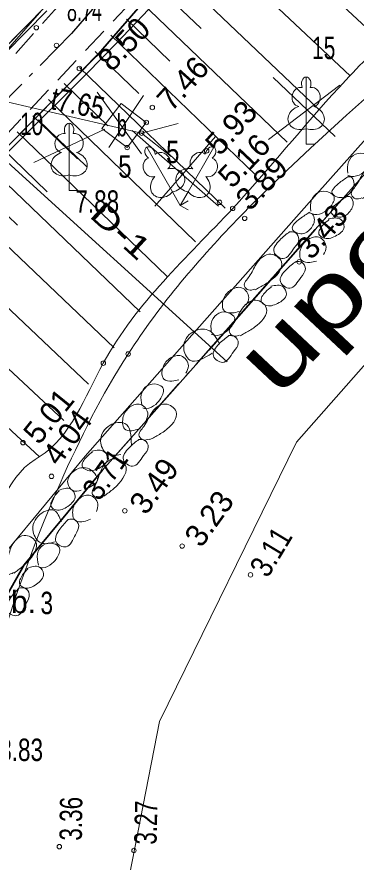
# Model space of a CAD drawing. Extents: x 514052 to 514314, y 297701 to 297876.
# Drawn here: x 514244.06 to 514251.62, y 297772.58 to 297791.45 of the extents above; entities that cross this region are included whole.
import ezdxf
from ezdxf.enums import TextEntityAlignment as Align

# ---------------------------------------------------------------- set-up
doc = ezdxf.new("R2010")
doc.units = 0
doc.header["$LTSCALE"] = 0.2
doc.linetypes.add('DOT_DASHED', pattern=[7.7, 5, -1.2, 0.3, -1.2])
doc.linetypes.add('MEDIUM_DASHED', pattern=[4.5, 3, -1.5])
for name, color, linetype, lineweight in [('1', 7, 'Continuous', 13), ('11', 7, 'Continuous', 35), ('19', 7, 'Continuous', 25), ('28', 7, 'Continuous', 13), ('3', 7, 'Continuous', 13), ('35', 7, 'Continuous', 25), ('5', 7, 'Continuous', 13), ('55', 7, 'Continuous', 13), ('56', 7, 'Continuous', 13), ('6', 7, 'Continuous', 13), ('61', 7, 'Continuous', 13), ('62', 7, 'Continuous', 13), ('63', 7, 'Continuous', 13)]:
    doc.layers.add(name, color=color, linetype=linetype, lineweight=lineweight)
for name, color, linetype in [('12', 7, 'Continuous'), ('15', 7, 'Continuous'), ('27', 7, 'Continuous'), ('8', 7, 'Continuous')]:
    doc.layers.add(name, color=color, linetype=linetype)

msp = doc.modelspace()

# ---------------------------------------------------------------- linework, layer by layer
at = {"layer": '1'}
for p, q in [((514248.911, 297793.941), (514252.207, 297790.881)), ((514248.228, 297793.211), (514251.49, 297790.135)), ((514247.54, 297792.484), (514250.781, 297789.394)), ((514247.195, 297792.123), (514248.166, 297791.194)), ((514246.849, 297791.762), (514250.084, 297788.657)), ((514246.502, 297791.401), (514247.472, 297790.467)), ((514246.155, 297791.041), (514249.39, 297787.917)), ((514245.808, 297790.682), (514246.779, 297789.741)), ((514245.46, 297790.323), (514248.705, 297787.181)), ((514245.112, 297789.963), (514246.09, 297789.017)), ((514244.765, 297789.604), (514248.043, 297786.429)), ((514244.417, 297789.245), (514245.409, 297788.285)), ((514244.069, 297788.886), (514247.41, 297785.654)), ((514243.722, 297788.526), (514244.737, 297787.546)), ((514243.375, 297788.166), (514246.81, 297784.865)), ((514243.028, 297787.805), (514244.075, 297786.803)), ((514242.683, 297787.444), (514246.229, 297784.064)), ((514241.994, 297786.719), (514245.66, 297783.255)), ((514241.309, 297785.99), (514245.105, 297782.443)), ((514240.629, 297785.257), (514244.562, 297781.634))]:
    msp.add_line(p, q, dxfattribs=at)
at = {"layer": '1', "lineweight": 35}
msp.add_line((514241.977, 297789.912), (514248.75, 297783.755), dxfattribs=at)
at = {"layer": '1'}
msp.add_spline([(514260.862, 297805.466), (514258.749, 297804.839), (514257.459, 297803.011), (514254.953, 297800.933), (514250.105, 297795.245), (514240.136, 297784.718), (514236.07, 297778.812), (514235.246, 297774.955), (514233.92, 297771.109), (514234.456, 297764.804)], degree=3, dxfattribs=at)
at = {"layer": '19', "lineweight": 13}
msp.add_spline([(514243.205, 297765.058), (514242.936, 297773.769), (514245.025, 297781.038), (514246.54, 297783.925), (514249.054, 297787.013), (514257.225, 297795.21), (514260.154, 297798.886), (514267.863, 297801.516), (514273.305, 297805.826), (514276.583, 297807.615)], degree=3, dxfattribs=at)
at = {"layer": '28'}
msp.add_lwpolyline([(514247.653, 297789.07), (514246.842, 297788.857), (514247.499, 297788.336)], dxfattribs=at)
at = {"layer": '3'}
msp.add_line((514226.333, 297793.626), (514246.842, 297788.857), dxfattribs=at)
at = {"layer": '35'}
msp.add_lwpolyline([(514231.97, 297771.331), (514233.541, 297774.128), (514233.667, 297780.485), (514240.255, 297787.177), (514246.843, 297793.868), (514250.774, 297798.68), (514254.387, 297803.352), (514256.058, 297805.511), (514258.694, 297808.915), (514260.151, 297809.248), (514268.632, 297811.186)], dxfattribs=at)
at = {"layer": '35', "lineweight": 35}
msp.add_lwpolyline([(514271.3, 297810.152), (514259.606, 297807.499), (514252.681, 297798.474), (514245.829, 297790.57), (514238.515, 297783.139), (514236.323, 297779.764), (514235.19, 297775.821), (514235.133, 297773.758), (514233.372, 297770.559)], dxfattribs=at)
at = {"layer": '5'}
for p, q in [((514250.51, 297790.109), (514250.51, 297788.956)), ((514250.6, 297789.877), (514250.599, 297789.878)), ((514245.225, 297789.079), (514245.225, 297787.926)), ((514250.51, 297788.956), (514250.51, 297788.609)), ((514245.315, 297788.847), (514245.314, 297788.848)), ((514250.51, 297788.609), (514250.71, 297788.609)), ((514246.954, 297788.544), (514247.53, 297787.546)), ((514247.148, 297788.388), (514247.146, 297788.388)), ((514248.454, 297788.544), (514247.877, 297787.546)), ((514248.415, 297788.298), (514248.415, 297788.299)), ((514245.225, 297787.926), (514245.225, 297787.579)), ((514245.225, 297787.579), (514245.425, 297787.579)), ((514247.53, 297787.546), (514247.704, 297787.245)), ((514247.877, 297787.546), (514247.704, 297787.245)), ((514247.704, 297787.245), (514247.877, 297787.345)), ((514247.704, 297787.245), (514247.877, 297787.145))]:
    msp.add_line(p, q, dxfattribs=at)
for centre, major_axis, ratio, start_param, end_param in [((514250.5104, 297789.9592), (0, -0.1499), 0.707107, 3.1453698, 5.2874846), ((514250.5095, 297789.9592), (0, -0.1499), 0.707107, 0.9957007, 3.1378155), ((514250.6382, 297789.6644), (0.0387, -0.2124), 0.861323, 6.2831853, 9.424778), ((514250.3817, 297789.6644), (-0.0387, -0.2124), 0.861323, 3.1415927, 6.2831853), ((514250.4204, 297789.2021), (0.3068, 0.0951), 0.814445, 1.5707963, 4.7520146), ((514250.5995, 297789.2021), (-0.3068, 0.0951), 0.814445, 1.5311707, 4.712389), ((514245.2254, 297788.9292), (0, -0.1499), 0.707107, 3.1453698, 5.2874846), ((514245.2245, 297788.9292), (0, -0.1499), 0.707107, 0.9957007, 3.1378155), ((514245.0967, 297788.6344), (-0.0387, -0.2124), 0.861323, 3.1415927, 6.2831853), ((514245.3532, 297788.6344), (0.0387, -0.2124), 0.861323, 6.2831853, 9.424778), ((514245.1354, 297788.1721), (0.3068, 0.0951), 0.814445, 1.5707963, 4.7520146), ((514245.3145, 297788.1721), (-0.3068, 0.0951), 0.814445, 1.5311707, 4.712389), ((514247.0293, 297788.4145), (0.075, -0.1298), 0.707107, 3.1453698, 5.2874846), ((514247.0286, 297788.4141), (0.075, -0.1298), 0.707107, 0.9957007, 3.1378155), ((514247.2875, 297788.2231), (0.1397, -0.1646), 0.861323, 6.2831853, 9.424778), ((514248.1204, 297788.2231), (-0.1397, -0.1646), 0.861323, 3.1415927, 6.2831853), ((514248.3793, 297788.4141), (-0.075, -0.1298), 0.707107, 3.1453698, 5.2874846), ((514248.3786, 297788.4145), (-0.075, -0.1298), 0.707107, 0.9957007, 3.1378155), ((514247.0652, 297788.0948), (0.0727, -0.2033), 0.861323, 3.1415927, 6.2831853), ((514248.3427, 297788.0948), (-0.0727, -0.2033), 0.861323, 6.2831853, 9.424778), ((514247.4851, 297787.8034), (-0.3133, -0.071), 0.814445, 1.5311707, 4.712389), ((514247.9228, 297787.8034), (0.3133, -0.071), 0.814445, 1.5707963, 4.7520146), ((514247.3299, 297787.7138), (0.2182, 0.2358), 0.814445, 1.5707963, 4.7520146), ((514248.078, 297787.7138), (-0.2182, 0.2358), 0.814445, 1.5311707, 4.712389)]:
    msp.add_ellipse(centre, major_axis=major_axis, ratio=ratio, start_param=start_param, end_param=end_param, dxfattribs=at)
at = {"layer": '55'}
for points in [[(514217.339, 297769.84), (514231.97, 297771.331), (514233.541, 297774.128), (514233.602, 297778.964), (514248.877, 297796.499), (514258.817, 297808.985), (514270.863, 297811.577), (514272.894, 297813.849)], [(514245.484, 297761.608), (514245.786, 297768.251), (514247.238, 297775.723), (514250.297, 297781.961), (514257.654, 297790.318), (514259.345, 297792.1), (514261.879, 297793.446), (514269.393, 297799.625), (514276.431, 297803.309), (514278.49, 297803.954), (514281.804, 297808.459), (514282.968, 297810.375)]]:
    msp.add_lwpolyline(points, dxfattribs=at)
at = {"layer": '56'}
msp.add_lwpolyline([(514246.518, 297788.534), (514246.945, 297789.095), (514246.384, 297789.522), (514245.957, 297788.961)], close=True, dxfattribs=at)
at = {"layer": '6'}
for centre in [(514244.4942, 297791.2095), (514244.9429, 297790.8151), (514245.452, 297790.3001), (514247.0809, 297789.4291), (514246.9449, 297789.0952), (514246.8419, 297788.8572), (514246.518, 297788.5341), (514248.29, 297788.4611), (514248.577, 297787.3121), (514248.871, 297787.1761), (514249.1399, 297786.9531), (514250.3529, 297785.9841), (514246.54, 297783.9251), (514245.9869, 297783.7231), (514244.196, 297781.9482), (514244.833, 297781.1942), (514246.4659, 297780.4261), (514247.7435, 297779.6386), (514249.2683, 297778.9954), (514245.0071, 297772.9269), (514246.6698, 297772.8415)]:
    msp.add_circle(centre, 0.05, dxfattribs=at)
at = {"layer": '61'}
msp.add_lwpolyline([(514219.342, 297770.059), (514231.967, 297771.335), (514233.539, 297774.175), (514233.667, 297780.485), (514246.843, 297793.868)], dxfattribs=at)
at = {"layer": '62'}
msp.add_spline([(514242.228, 297765.875), (514240.809, 297773.912), (514243.289, 297779.448), (514244.466, 297781.572), (514244.559, 297781.63), (514245.987, 297783.723), (514248.871, 297787.176), (514251.243, 297789.878), (514252.476, 297791.159), (514253.723, 297792.429), (514256.513, 297795.415), (514260.533, 297799.834), (514263.587, 297801.907), (514261.268, 297805.481)], degree=3, dxfattribs=at)
at = {"layer": '63'}
for p, q in [((514249.773, 297790.097), (514251.158, 297788.78)), ((514249.671, 297788.712), (514251.259, 297789.928)), ((514245.847, 297789.77), (514246.835, 297788.394)), ((514246.885, 297789.694), (514246.108, 297788.537)), ((514244.536, 297789.151), (514245.617, 297788.104)), ((514246.023, 297788.948), (514244.435, 297788.205)), ((514246.631, 297788.915), (514248.557, 297787.225)), ((514248.489, 297788.78), (514247.138, 297787.225))]:
    msp.add_line(p, q, dxfattribs=at)
at = {"layer": '63', "linetype": 'MEDIUM_DASHED'}
for points in [[(514231.583, 297765.652), (514232.855, 297769.107), (514235.126, 297775.062), (514235.802, 297779.27), (514240.035, 297784.801), (514250.098, 297795.488), (514254.893, 297801.043), (514257.448, 297803.118), (514259.485, 297807.223), (514261.814, 297808.455), (514265.145, 297808.86), (514272.105, 297811.112)], [(514249.225, 297796.455), (514239.453, 297785.495), (514234.344, 297779.635), (514234.008, 297775.04), (514233.159, 297771.888), (514231.647, 297770.296), (514228.019, 297768.169)]]:
    msp.add_lwpolyline(points, dxfattribs=at)
at = {"layer": '63', "linetype": 'DOT_DASHED', "lineweight": 25}
for points in [[(514271.134, 297810.883), (514259.176, 297808.17), (514252.1, 297798.948), (514245.278, 297791.079), (514237.927, 297783.611), (514235.633, 297780.079), (514234.443, 297775.937), (514234.388, 297773.96), (514232.332, 297770.225), (514229.92, 297766.887)], [(514241.744, 297765.925), (514242.057, 297774.207), (514242.797, 297776.707), (514244.225, 297779.218), (514245.964, 297781.323), (514250.712, 297786.706), (514257.523, 297794.362), (514261.299, 297799.094), (514264.423, 297802.109), (514265.043, 297802.596), (514265.222, 297802.656), (514267.352, 297803.342), (514273.537, 297806.201)]]:
    msp.add_lwpolyline(points, dxfattribs=at)
at = {"layer": '63', "lineweight": 35}
msp.add_lwpolyline([(514241.744, 297765.925), (514242.057, 297774.207), (514242.797, 297776.707), (514244.225, 297779.218), (514245.094, 297780.271), (514245.964, 297781.323), (514248.338, 297784.015), (514250.712, 297786.706), (514254.118, 297790.534), (514257.523, 297794.362), (514259.411, 297796.728), (514261.299, 297799.094), (514262.861, 297800.601), (514264.423, 297802.109), (514265.043, 297802.596), (514267.352, 297803.342), (514273.537, 297806.201)], dxfattribs=at)
at = {"layer": '63'}
for points in [[(514249.255, 297794.522), (514245.829, 297790.57), (514241.829, 297786.505), (514238.515, 297783.139), (514236.314, 297779.769), (514235.179, 297775.815), (514235.126, 297773.769), (514232.94, 297769.786), (514230.528, 297766.448), (514229.312, 297767.326), (514231.675, 297770.587), (514233.643, 297774.162), (514233.696, 297776.053), (514234.943, 297780.394), (514237.339, 297784.083), (514241.033, 297787.835), (514244.727, 297791.588)], [(514233.812, 297771.282), (514235.126, 297773.769), (514235.179, 297775.815), (514236.314, 297779.769), (514238.515, 297783.139), (514239.32, 297783.956), (514239.882, 297784.527), (514240.622, 297785.277), (514243.036, 297787.732), (514245.182, 297789.914), (514246.011, 297790.776), (514246.248, 297791.053), (514247.856, 297792.907)], [(514253.744, 297790.866), (514250.746, 297787.504), (514247.963, 297784.346), (514245.584, 297781.648), (514243.812, 297779.503), (514242.875, 297777.861), (514242.334, 297776.904), (514242.334, 297776.904), (514241.56, 297774.289), (514241.402, 297770.117)]]:
    msp.add_lwpolyline(points, dxfattribs=at)
at = {"layer": '63', "lineweight": 35}
msp.add_spline([(514235.586, 297788.069), (514238.834, 297789.344), (514246.139, 297795.966), (514248.394, 297799.596), (514253.835, 297808.327)], degree=3, dxfattribs=at)
at = {"layer": '63'}
for points in [[(514251.438, 297787.964), (514251.454, 297788.217), (514251.611, 297788.387), (514251.852, 297788.382), (514251.955, 297788.286), (514251.875, 297788.069), (514251.74, 297787.95), (514251.517, 297787.891), (514251.44, 297787.915)], [(514251.749, 297787.41), (514251.611, 297787.392), (514251.52, 297787.477), (514251.626, 297787.693), (514251.779, 297787.965), (514252.111, 297788.192), (514252.343, 297788.023), (514252.083, 297787.586), (514251.861, 297787.452), (514251.762, 297787.397)], [(514251.466, 297787.896), (514251.257, 297787.753), (514251.089, 297787.518), (514251.307, 297787.418), (514251.491, 297787.527), (514251.575, 297787.762), (514251.5, 297787.879), (514251.441, 297787.879)], [(514250.614, 297787.114), (514250.63, 297787.367), (514250.787, 297787.537), (514251.028, 297787.532), (514251.131, 297787.436), (514251.051, 297787.219), (514250.916, 297787.1), (514250.693, 297787.041), (514250.616, 297787.065)], [(514251.445, 297787.459), (514251.236, 297787.316), (514251.068, 297787.081), (514251.286, 297786.981), (514251.47, 297787.09), (514251.554, 297787.325), (514251.479, 297787.442), (514251.42, 297787.442)], [(514250.581, 297787.089), (514250.372, 297786.946), (514250.204, 297786.711), (514250.422, 297786.611), (514250.606, 297786.72), (514250.69, 297786.955), (514250.615, 297787.072), (514250.556, 297787.072)], [(514251.008, 297786.941), (514251.286, 297786.926), (514251.356, 297786.765), (514251.161, 297786.557), (514250.887, 297786.521), (514250.795, 297786.605), (514250.889, 297786.81), (514251.023, 297786.928)], [(514250.14, 297786.655), (514249.92, 297786.47), (514249.793, 297786.201), (514249.999, 297786.058), (514250.243, 297786.294), (514250.348, 297786.488), (514250.267, 297786.635), (514250.14, 297786.655)], [(514250.897, 297786.146), (514250.955, 297786.312), (514250.795, 297786.533), (514250.557, 297786.486), (514250.39, 297786.279), (514250.411, 297786.014), (514250.589, 297785.971), (514250.74, 297786.002)], [(514249.363, 297785.374), (514249.225, 297785.356), (514249.134, 297785.441), (514249.24, 297785.657), (514249.393, 297785.929), (514249.725, 297786.156), (514249.957, 297785.987), (514249.697, 297785.55), (514249.475, 297785.416), (514249.376, 297785.361)], [(514250.284, 297785.993), (514250.064, 297785.808), (514249.937, 297785.539), (514250.143, 297785.396), (514250.387, 297785.632), (514250.492, 297785.826), (514250.411, 297785.973), (514250.284, 297785.993)], [(514249.173, 297785.018), (514249.231, 297785.184), (514249.071, 297785.405), (514248.833, 297785.358), (514248.666, 297785.151), (514248.687, 297784.886), (514248.865, 297784.843), (514249.016, 297784.874)], [(514249.721, 297785.439), (514249.999, 297785.424), (514250.069, 297785.263), (514249.874, 297785.055), (514249.6, 297785.019), (514249.508, 297785.103), (514249.602, 297785.308), (514249.736, 297785.426)], [(514249.027, 297784.347), (514248.889, 297784.329), (514248.798, 297784.414), (514248.904, 297784.63), (514249.057, 297784.902), (514249.389, 297785.129), (514249.621, 297784.96), (514249.361, 297784.523), (514249.139, 297784.389), (514249.04, 297784.334)], [(514248.393, 297784.417), (514248.409, 297784.67), (514248.566, 297784.84), (514248.807, 297784.835), (514248.91, 297784.739), (514248.83, 297784.522), (514248.695, 297784.403), (514248.472, 297784.344), (514248.395, 297784.368)], [(514248.58, 297784.149), (514248.318, 297784.462), (514247.992, 297784.424), (514247.779, 297784.064), (514247.915, 297783.791), (514248.414, 297783.947)], [(514248.788, 297784.337), (514248.568, 297784.152), (514248.441, 297783.883), (514248.647, 297783.74), (514248.891, 297783.976), (514248.996, 297784.17), (514248.915, 297784.317), (514248.788, 297784.337)], [(514247.825, 297783.497), (514247.883, 297783.663), (514247.723, 297783.884), (514247.485, 297783.837), (514247.318, 297783.63), (514247.339, 297783.365), (514247.517, 297783.322), (514247.668, 297783.353)], [(514246.857, 297782.769), (514246.833, 297783.021), (514246.962, 297783.214), (514247.2, 297783.247), (514247.317, 297783.168), (514247.272, 297782.941), (514247.157, 297782.802), (514246.946, 297782.709), (514246.867, 297782.721)], [(514246.946, 297782.441), (514246.977, 297782.614), (514246.785, 297782.807), (514246.557, 297782.724), (514246.424, 297782.493), (514246.486, 297782.235), (514246.669, 297782.22), (514246.813, 297782.274)], [(514247.015, 297782.028), (514246.877, 297782.01), (514246.786, 297782.095), (514246.892, 297782.311), (514247.045, 297782.583), (514247.377, 297782.81), (514247.609, 297782.641), (514247.349, 297782.204), (514247.127, 297782.07), (514247.028, 297782.015)], [(514246.616, 297781.899), (514246.466, 297782.377), (514246.14, 297782.339), (514245.927, 297781.979), (514246.063, 297781.706), (514246.379, 297781.681)], [(514246.782, 297782.018), (514246.562, 297781.833), (514246.435, 297781.564), (514246.641, 297781.421), (514246.885, 297781.657), (514246.99, 297781.851), (514246.909, 297781.998), (514246.782, 297782.018)], [(514245.732, 297781.757), (514246.01, 297781.742), (514246.08, 297781.581), (514245.885, 297781.373), (514245.611, 297781.337), (514245.519, 297781.421), (514245.613, 297781.626), (514245.747, 297781.744)], [(514245.986, 297780.759), (514245.852, 297780.72), (514245.749, 297780.79), (514245.82, 297781.02), (514245.929, 297781.312), (514246.221, 297781.588), (514246.477, 297781.458), (514246.288, 297780.985), (514246.09, 297780.818), (514246.001, 297780.749)], [(514245.495, 297780.886), (514245.311, 297780.878), (514245.194, 297781.046), (514245.294, 297781.28), (514245.554, 297781.389), (514245.822, 297781.222), (514245.856, 297781.104), (514245.747, 297780.987), (514245.604, 297780.911)], [(514244.987, 297780.881), (514245.264, 297780.909), (514245.358, 297780.761), (514245.198, 297780.525), (514244.933, 297780.447), (514244.829, 297780.516), (514244.889, 297780.733), (514245.003, 297780.87)], [(514245.832, 297780.408), (514245.863, 297780.581), (514245.671, 297780.774), (514245.443, 297780.691), (514245.31, 297780.46), (514245.372, 297780.202), (514245.555, 297780.187), (514245.699, 297780.241)], [(514245.046, 297780.183), (514244.893, 297780.435), (514244.577, 297780.347), (514244.423, 297779.958), (514244.6, 297779.71), (514244.916, 297779.734)], [(514245.207, 297780.234), (514245.019, 297780.017), (514244.935, 297779.731), (514245.161, 297779.622), (514245.365, 297779.893), (514245.439, 297780.101), (514245.336, 297780.234), (514245.207, 297780.234)], [(514243.985, 297779.046), (514243.851, 297779.007), (514243.748, 297779.077), (514243.819, 297779.307), (514243.928, 297779.599), (514244.22, 297779.875), (514244.476, 297779.745), (514244.287, 297779.272), (514244.089, 297779.105), (514244, 297779.036)], [(514244.543, 297779.214), (514244.519, 297779.466), (514244.648, 297779.659), (514244.886, 297779.692), (514245.003, 297779.613), (514244.958, 297779.386), (514244.843, 297779.247), (514244.632, 297779.154), (514244.553, 297779.166)], [(514244.286, 297779.141), (514244.563, 297779.169), (514244.657, 297779.021), (514244.497, 297778.785), (514244.232, 297778.707), (514244.128, 297778.776), (514244.188, 297778.993), (514244.302, 297779.13)], [(514244.106, 297778.699), (514243.918, 297778.482), (514243.834, 297778.196), (514244.06, 297778.087), (514244.264, 297778.358), (514244.338, 297778.566), (514244.235, 297778.699), (514244.106, 297778.699)]]:
    msp.add_spline(points, degree=3, dxfattribs=at)

# ---------------------------------------------------------------- texts
at = {"layer": '11'}
for s, rotation, width, p in [('t7.65', 348.15, 0.8, (514245.3687, 297789.2783)), ('D-1', 317.647, 1.4, (514246.2111, 297786.4905))]:
    msp.add_text(s, height=0.5, rotation=rotation, dxfattribs=dict(at, width=width)).set_placement(p, align=Align.CENTER)
at = {"layer": '12'}
for s, width, p in [(' 15', 0.7, (514250.51, 297790.509)), (' 10', 0.7, (514243.998, 297788.812)), (' 5', 0.8, (514247.238, 297788.187)), (' 5', 0.8, (514246.171, 297787.863))]:
    msp.add_text(s, height=0.5, dxfattribs=dict(at, width=width)).set_placement(p)
at = {"layer": '15', "width": 0.6}
msp.add_text('b', height=0.5, dxfattribs=at).set_placement((514246.288, 297788.782))
at = {"layer": '27', "width": 1.4}
msp.add_text('upe Íekava', height=1.5, rotation=46.796, dxfattribs=at).set_placement((514249.884, 297782.926))
at = {"layer": '6'}
msp.add_text('urb.', height=0.5, dxfattribs=at).set_placement((514243.336, 297778.142))
at = {"layer": '6', "width": 0.75}
msp.add_text('3', height=0.5, dxfattribs=at).set_placement((514244.7265, 297778.119), align=Align.CENTER)
at = {"layer": '8'}
for s, width, p in [('8.74', 0.6, (514245.177, 297791.358)), (' 7.88', 0.75, (514245.225, 297787.079)), (' 3.83', 0.75, (514243.528, 297774.84))]:
    msp.add_text(s, height=0.5, dxfattribs=dict(at, width=width)).set_placement(p)
for s, rotation, p in [(' 8.50', 46.059, (514246.046, 297790.071)), (' 7.46', 48.037, (514247.386, 297789.179)), (' 5.93', 48.163, (514248.465, 297788.19)), (' 5.16', 46.615, (514248.732, 297787.465)), (' 3.89', 46.961, (514249.13, 297786.96)), (' 3.43', 49.314, (514250.506, 297785.865)), (' 5.01', 51.068, (514244.436, 297781.733)), (' 4.04', 53.579, (514244.886, 297781.249)), (' 3.49', 54.114, (514246.828, 297780.156)), (' 3.23', 54.373, (514248.061, 297779.428))]:
    msp.add_text(s, height=0.5, rotation=rotation, dxfattribs=at).set_placement(p)
for s, rotation, width, p in [(' 3.71', 55.025, 0.9, (514245.8, 297780.483)), (' 3.11', 58.945, 0.85, (514249.572, 297778.773)), (' 3.36', 89.272, 0.75, (514245.507, 297772.921)), (' 3.27', 88.653, 0.75, (514247.17, 297772.83))]:
    msp.add_text(s, height=0.5, rotation=rotation, dxfattribs=dict(at, width=width)).set_placement(p)

doc.saveas('drawing.dxf')
